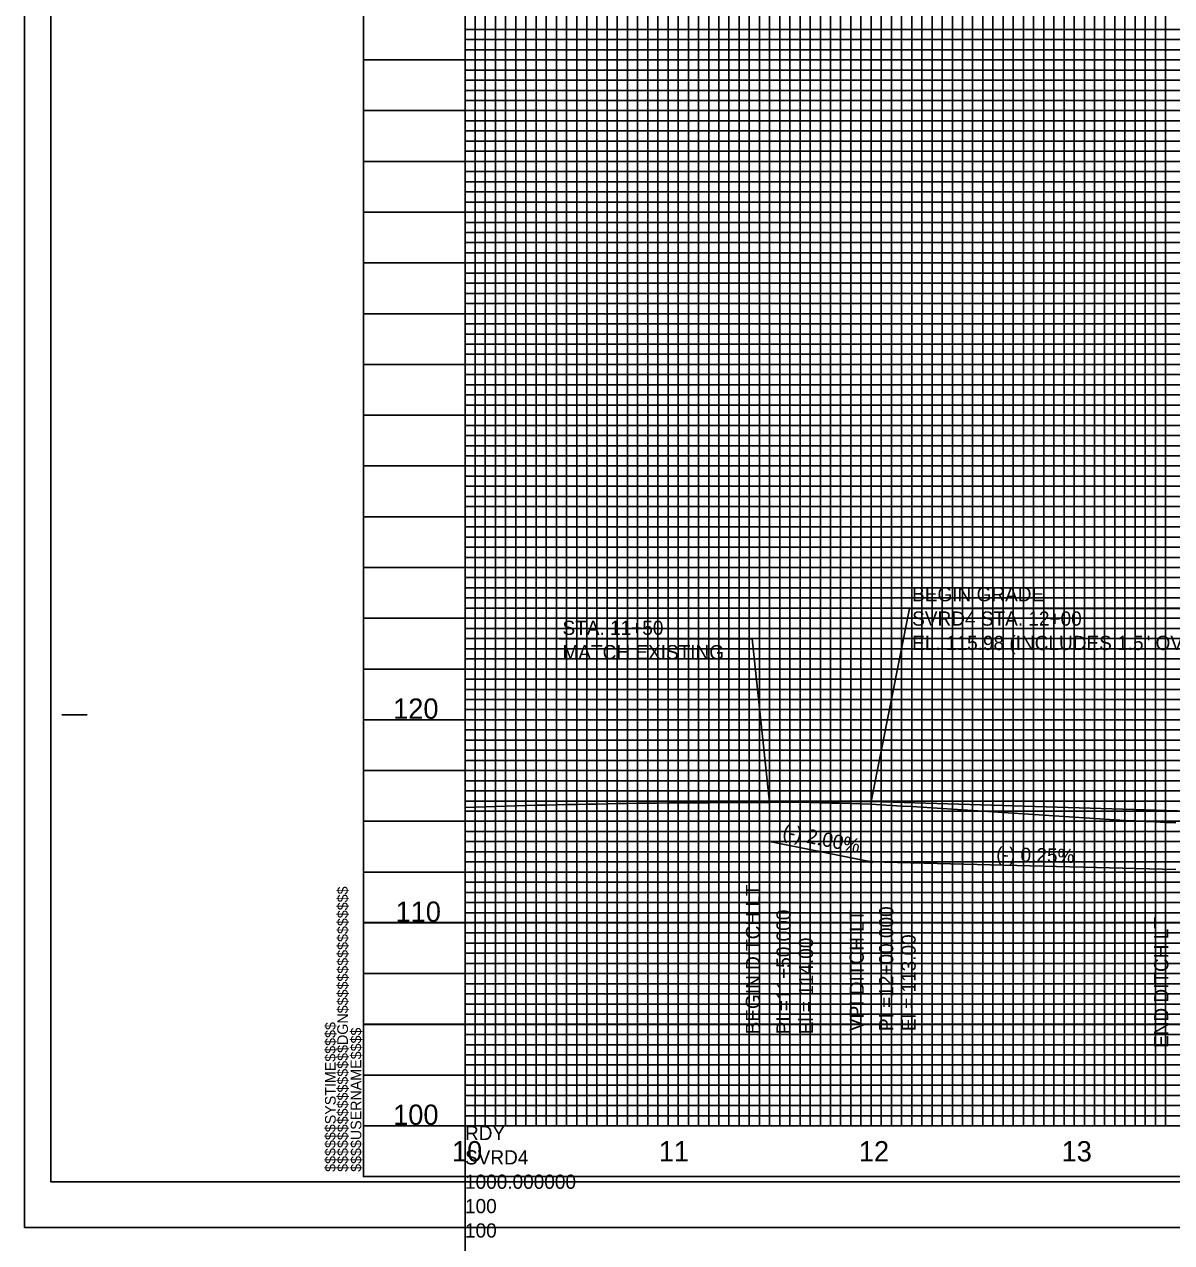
# Model space of a CAD drawing. Extents: x 2345490 to 2436403, y 465165 to 573888.
# Drawn here: x 2381550 to 2382115, y 495035 to 495635 of the extents above; entities that cross this region are included whole.
import ezdxf

# ---------------------------------------------------------------- set-up
doc = ezdxf.new("R2010")
doc.units = 0
for name, color, linetype in [('Old_Level_1', 7, 'Continuous'), ('Old_Level_18', 7, 'Continuous'), ('Old_Level_2', 7, 'Continuous'), ('Old_Level_3', 7, 'Continuous'), ('Old_Level_40', 7, 'Continuous'), ('Old_Level_41', 7, 'Continuous'), ('Old_Level_42', 7, 'Continuous'), ('Old_Level_43', 7, 'Continuous'), ('Old_Level_50', 7, 'Continuous'), ('Old_Level_51', 7, 'Continuous'), ('Old_Level_52', 7, 'Continuous'), ('Old_Level_57', 7, 'Continuous'), ('Old_Level_62', 7, 'Continuous'), ('Old_Level_63', 7, 'Continuous')]:
    doc.layers.add(name, color=color, linetype=linetype)

msp = doc.modelspace()

# ---------------------------------------------------------------- linework, layer by layer
at = {"layer": 'Old_Level_1'}
msp.add_lwpolyline([(2381766.799, 495249.40325), (2381771.799, 495249.5755), (2381776.799, 495249.74775), (2381781.799, 495249.92), (2381786.799, 495250.09225), (2381791.799, 495250.26425), (2381796.799, 495250.4135), (2381801.799, 495250.52025), (2381806.799, 495250.627), (2381811.799, 495250.7335), (2381816.799, 495250.84025), (2381821.799, 495250.947), (2381826.799, 495251.0435), (2381831.799, 495251.15), (2381836.799, 495251.25675), (2381841.799, 495251.3635), (2381846.799, 495251.47025), (2381851.799, 495251.57575), (2381856.799, 495251.61225), (2381861.799, 495251.644), (2381866.799, 495251.67575), (2381871.799, 495251.70725), (2381876.799, 495251.739), (2381881.799, 495251.77025), (2381886.799, 495251.78975), (2381891.799, 495251.8215), (2381896.799, 495251.853), (2381901.799, 495251.8845), (2381906.799, 495251.916), (2381911.799, 495251.9475), (2381916.799, 495251.979), (2381921.799, 495252.0105), (2381926.799, 495252.042), (2381931.799, 495252.0035), (2381936.799, 495251.8815), (2381941.799, 495251.75925), (2381946.799, 495251.63725), (2381951.799, 495251.51525), (2381956.799, 495251.39325), (2381961.799, 495251.27375), (2381966.799, 495251.117), (2381971.799, 495250.8055), (2381976.799, 495250.4905), (2381981.799, 495250.17525), (2381986.799, 495249.86025), (2381991.799, 495249.545), (2381996.799, 495249.23), (2382001.799, 495248.91675), (2382006.799, 495248.6015), (2382011.799, 495248.28625), (2382016.799, 495247.97075), (2382021.799, 495247.6555), (2382026.799, 495247.34025), (2382031.799, 495247.0215), (2382036.799, 495246.697), (2382041.799, 495246.37225), (2382046.799, 495246.04775), (2382051.799, 495245.723), (2382056.799, 495245.3975), (2382061.799, 495245.0645), (2382066.799, 495244.7315), (2382071.799, 495244.39825), (2382076.799, 495244.06525), (2382081.799, 495243.73225), (2382086.799, 495243.399), (2382091.799, 495243.09625), (2382096.799, 495242.8485), (2382101.799, 495242.601), (2382106.799, 495242.35325), (2382111.799, 495242.10525), (2382116.799, 495241.85425)], dxfattribs=at)
at = {"layer": 'Old_Level_18'}
msp.add_line((2381716.79875, 495067.6345), (2381716.79875, 495067.6345), dxfattribs=at)
msp.add_line((2381716.79875, 495067.6345), (2381716.79875, 495067.6345), dxfattribs=at)
msp.add_lwpolyline([(2383216.79875, 496117.6345), (2381716.79875, 496117.6345), (2381716.79875, 495067.6345), (2383216.79875, 495067.6345)], close=True, dxfattribs=at)
at = {"layer": 'Old_Level_2'}
for p, q in [((2381966.799, 495252.4345), (2381985.7585, 495347.449)), ((2381985.7585, 495347.449), (2382194.836, 495347.449)), ((2381813.15575, 495332.47475), (2381908.162, 495332.47475)), ((2381916.79875, 495251.979), (2381908.162, 495332.47475)), ((2381966.799, 495252.4345), (2381916.79875, 495251.979)), ((2381966.799, 495252.4345), (2382191.799, 495245.4595))]:
    msp.add_line(p, q, dxfattribs=at)
at = {"layer": 'Old_Level_3'}
for p, q in [((2381916.799, 495232.6345), (2381966.799, 495222.6345)), ((2381916.799, 495232.6345), (2381916.799, 495136.33353)), ((2381966.799, 495222.6345), (2382116.799, 495218.9345)), ((2381966.799, 495222.6345), (2381966.799, 495136.87267))]:
    msp.add_line(p, q, dxfattribs=at)
msp.add_circle((2381966.799, 495222.6345), 0.5, dxfattribs=at)
at = {"layer": 'Old_Level_40'}
msp.add_line((2381716.79875, 495067.6345), (2381716.79875, 495067.6345), dxfattribs=at)
msp.add_line((2381716.79875, 495067.6345), (2381716.79875, 495067.6345), dxfattribs=at)
msp.add_line((2381716.79875, 495067.6345), (2381716.79875, 495067.6345), dxfattribs=at)
msp.add_line((2381716.79875, 495067.6345), (2381716.79875, 495067.6345), dxfattribs=at)
at = {"layer": 'Old_Level_41'}
for p, q in [((2381568.29875, 495295.1345), (2381580.79875, 495295.1345)), ((2383216.79875, 495092.6345), (2381716.79875, 495092.6345))]:
    msp.add_line(p, q, dxfattribs=at)
for points in [[(2381716.79875, 496117.6345), (2381766.79875, 496117.6345), (2381766.79875, 495092.6345), (2381816.79875, 495092.6345), (2381816.79875, 496117.6345), (2381866.79875, 496117.6345), (2381866.79875, 495092.6345), (2381916.79875, 495092.6345), (2381916.79875, 496117.6345), (2381966.79875, 496117.6345), (2381966.79875, 495092.6345), (2382016.79875, 495092.6345), (2382016.79875, 496117.6345), (2382066.79875, 496117.6345), (2382066.79875, 495092.6345), (2382116.79875, 495092.6345)], [(2381791.79875, 495092.6345), (2381791.79875, 496117.6345), (2381841.79875, 496117.6345), (2381841.79875, 495092.6345), (2381891.79875, 495092.6345), (2381891.79875, 496117.6345), (2381941.79875, 496117.6345), (2381941.79875, 495092.6345), (2381991.79875, 495092.6345), (2381991.79875, 496117.6345), (2382041.79875, 496117.6345), (2382041.79875, 495092.6345), (2382091.79875, 495092.6345), (2382091.79875, 496117.6345), (2382141.79875, 496117.6345)], [(2383216.79875, 495617.6345), (2381716.79875, 495617.6345), (2381716.79875, 495567.6345), (2383216.79875, 495567.6345)], [(2383216.79875, 495517.6345), (2381716.79875, 495517.6345), (2381716.79875, 495467.6345), (2383216.79875, 495467.6345)], [(2383216.79875, 495442.6345), (2381716.79875, 495442.6345), (2381716.79875, 495492.6345), (2383216.79875, 495492.6345)], [(2383216.79875, 495417.6345), (2381716.79875, 495417.6345), (2381716.79875, 495367.6345), (2383216.79875, 495367.6345)], [(2383216.79875, 495342.6345), (2381716.79875, 495342.6345), (2381716.79875, 495392.6345), (2383216.79875, 495392.6345)], [(2383216.79875, 495317.6345), (2381716.79875, 495317.6345), (2381716.79875, 495267.6345), (2383216.79875, 495267.6345)], [(2383216.79875, 495217.6345), (2381716.79875, 495217.6345), (2381716.79875, 495167.6345), (2383216.79875, 495167.6345)], [(2383216.79875, 495142.6345), (2381716.79875, 495142.6345), (2381716.79875, 495192.6345), (2383216.79875, 495192.6345)], [(2383216.79875, 495117.6345), (2381716.79875, 495117.6345)], [(2381754.29875, 495067.6345), (2381754.29875, 495067.6345)]]:
    msp.add_lwpolyline(points, dxfattribs=at)
at = {"layer": 'Old_Level_42'}
for points in [[(2383216.79875, 495542.6345), (2381716.79875, 495542.6345), (2381716.79875, 495592.6345), (2383216.79875, 495592.6345)], [(2383216.79875, 495242.6345), (2381716.79875, 495242.6345), (2381716.79875, 495292.6345), (2383216.79875, 495292.6345)]]:
    msp.add_lwpolyline(points, dxfattribs=at)
at = {"layer": 'Old_Level_43'}
for points in [[(2381771.79875, 496117.6345), (2381771.79875, 495092.6345), (2381776.79875, 495092.6345), (2381776.79875, 496117.6345)], [(2381781.79875, 496117.6345), (2381781.79875, 495092.6345), (2381786.79875, 495092.6345), (2381786.79875, 496117.6345)], [(2381796.79875, 496117.6345), (2381796.79875, 495092.6345), (2381801.79875, 495092.6345), (2381801.79875, 496117.6345)], [(2381806.79875, 496117.6345), (2381806.79875, 495092.6345), (2381811.79875, 495092.6345), (2381811.79875, 496117.6345)], [(2381821.79875, 496117.6345), (2381821.79875, 495092.6345), (2381826.79875, 495092.6345), (2381826.79875, 496117.6345)], [(2381831.79875, 496117.6345), (2381831.79875, 495092.6345), (2381836.79875, 495092.6345), (2381836.79875, 496117.6345)], [(2381846.79875, 496117.6345), (2381846.79875, 495092.6345), (2381851.79875, 495092.6345), (2381851.79875, 496117.6345)], [(2381856.79875, 496117.6345), (2381856.79875, 495092.6345), (2381861.79875, 495092.6345), (2381861.79875, 496117.6345)], [(2381871.79875, 496117.6345), (2381871.79875, 495092.6345), (2381876.79875, 495092.6345), (2381876.79875, 496117.6345)], [(2381881.79875, 496117.6345), (2381881.79875, 495092.6345), (2381886.79875, 495092.6345), (2381886.79875, 496117.6345)], [(2381896.79875, 496117.6345), (2381896.79875, 495092.6345), (2381901.79875, 495092.6345), (2381901.79875, 496117.6345)], [(2381906.79875, 496117.6345), (2381906.79875, 495092.6345), (2381911.79875, 495092.6345), (2381911.79875, 496117.6345)], [(2381921.79875, 496117.6345), (2381921.79875, 495092.6345), (2381926.79875, 495092.6345), (2381926.79875, 496117.6345)], [(2381931.79875, 495092.6345), (2381936.79875, 495092.6345), (2381936.79875, 496117.6345)], [(2381931.79875, 496117.6345), (2381931.79875, 495092.6345)], [(2381946.79875, 496117.6345), (2381946.79875, 495092.6345), (2381951.79875, 495092.6345), (2381951.79875, 496117.6345)], [(2381956.79875, 496117.6345), (2381956.79875, 495092.6345), (2381961.79875, 495092.6345), (2381961.79875, 496117.6345)], [(2381971.79875, 496117.6345), (2381971.79875, 495092.6345), (2381976.79875, 495092.6345), (2381976.79875, 496117.6345)], [(2381981.79875, 496117.6345), (2381981.79875, 495092.6345), (2381986.79875, 495092.6345), (2381986.79875, 496117.6345)], [(2381996.79875, 496117.6345), (2381996.79875, 495092.6345), (2382001.79875, 495092.6345), (2382001.79875, 496117.6345)], [(2382006.79875, 496117.6345), (2382006.79875, 495092.6345), (2382011.79875, 495092.6345), (2382011.79875, 496117.6345)], [(2382021.79875, 496117.6345), (2382021.79875, 495092.6345), (2382026.79875, 495092.6345), (2382026.79875, 496117.6345)], [(2382031.79875, 496117.6345), (2382031.79875, 495092.6345), (2382036.79875, 495092.6345), (2382036.79875, 496117.6345)], [(2382046.79875, 496117.6345), (2382046.79875, 495092.6345), (2382051.79875, 495092.6345), (2382051.79875, 496117.6345)], [(2382056.79875, 496117.6345), (2382056.79875, 495092.6345), (2382061.79875, 495092.6345), (2382061.79875, 496117.6345)], [(2382071.79875, 496117.6345), (2382071.79875, 495092.6345), (2382076.79875, 495092.6345), (2382076.79875, 496117.6345)], [(2382081.79875, 496117.6345), (2382081.79875, 495092.6345), (2382086.79875, 495092.6345), (2382086.79875, 496117.6345)], [(2382096.79875, 496117.6345), (2382096.79875, 495092.6345), (2382111.79875, 495092.6345), (2382111.79875, 496117.6345)], [(2382101.79875, 496117.6345), (2382101.79875, 495092.6345), (2382106.79875, 495092.6345), (2382106.79875, 496117.6345)], [(2382101.79875, 496117.0345), (2382101.79875, 495092.6345), (2382106.79875, 495092.6345), (2382106.79875, 496117.0345)], [(2383166.79875, 495632.6345), (2381766.79875, 495632.6345), (2381766.79875, 495627.6345), (2383166.79875, 495627.6345)], [(2383166.79875, 495622.6345), (2381766.79875, 495622.6345), (2381766.79875, 495612.6345), (2383166.79875, 495612.6345)], [(2383166.79875, 495607.6345), (2381766.79875, 495607.6345), (2381766.79875, 495602.6345), (2383166.79875, 495602.6345)], [(2383166.79875, 495597.6345), (2381766.79875, 495597.6345)], [(2381766.79875, 495587.6345), (2383166.79875, 495587.6345)], [(2383166.79875, 495582.6345), (2381766.79875, 495582.6345), (2381766.79875, 495577.6345), (2383166.79875, 495577.6345)], [(2383166.79875, 495572.6345), (2381766.79875, 495572.6345), (2381766.79875, 495562.6345), (2383166.79875, 495562.6345)], [(2383166.79875, 495557.6345), (2381766.79875, 495557.6345), (2381766.79875, 495552.6345), (2383166.79875, 495552.6345)], [(2383166.79875, 495547.6345), (2381766.79875, 495547.6345), (2381766.79875, 495537.6345), (2383166.79875, 495537.6345)], [(2383166.79875, 495532.6345), (2381766.79875, 495532.6345), (2381766.79875, 495527.6345), (2383166.79875, 495527.6345)], [(2383166.79875, 495522.6345), (2381766.79875, 495522.6345), (2381766.79875, 495512.6345), (2383166.79875, 495512.6345)], [(2383166.79875, 495507.6345), (2381766.79875, 495507.6345), (2381766.79875, 495502.6345), (2383166.79875, 495502.6345)], [(2383166.79875, 495497.6345), (2381766.79875, 495497.6345), (2381766.79875, 495487.6345), (2383166.79875, 495487.6345)], [(2383166.79875, 495482.6345), (2381766.79875, 495482.6345), (2381766.79875, 495477.6345), (2383166.79875, 495477.6345)], [(2383166.79875, 495472.6345), (2381766.79875, 495472.6345), (2381766.79875, 495462.6345), (2383166.79875, 495462.6345)], [(2383166.79875, 495457.6345), (2381766.79875, 495457.6345), (2381766.79875, 495452.6345), (2383166.79875, 495452.6345)], [(2383166.79875, 495447.6345), (2381766.79875, 495447.6345), (2381766.79875, 495437.6345), (2383166.79875, 495437.6345)], [(2383166.79875, 495432.6345), (2381766.79875, 495432.6345), (2381766.79875, 495427.6345), (2383166.79875, 495427.6345)], [(2383166.79875, 495422.6345), (2381766.79875, 495422.6345), (2381766.79875, 495412.6345), (2383166.79875, 495412.6345)], [(2383166.79875, 495407.6345), (2381766.79875, 495407.6345), (2381766.79875, 495402.6345), (2383166.79875, 495402.6345)], [(2383166.79875, 495397.6345), (2381766.79875, 495397.6345), (2381766.79875, 495387.6345), (2383166.79875, 495387.6345)], [(2383166.79875, 495382.6345), (2381766.79875, 495382.6345), (2381766.79875, 495377.6345), (2383166.79875, 495377.6345)], [(2383166.79875, 495372.6345), (2381766.79875, 495372.6345), (2381766.79875, 495362.6345), (2383166.79875, 495362.6345)], [(2383166.79875, 495357.6345), (2381766.79875, 495357.6345), (2381766.79875, 495352.6345), (2383166.79875, 495352.6345)], [(2383166.79875, 495347.6345), (2381766.79875, 495347.6345), (2381766.79875, 495337.6345), (2383166.79875, 495337.6345)], [(2383166.79875, 495332.6345), (2381766.79875, 495332.6345), (2381766.79875, 495327.6345), (2383166.79875, 495327.6345)], [(2383166.79875, 495322.6345), (2381766.79875, 495322.6345), (2381766.79875, 495312.6345), (2383166.79875, 495312.6345)], [(2383166.79875, 495307.6345), (2381766.79875, 495307.6345), (2381766.79875, 495302.6345), (2383166.79875, 495302.6345)], [(2383166.79875, 495297.6345), (2381766.79875, 495297.6345)], [(2381766.79875, 495287.6345), (2383166.79875, 495287.6345)], [(2383166.79875, 495282.6345), (2381766.79875, 495282.6345), (2381766.79875, 495277.6345), (2383166.79875, 495277.6345)], [(2383166.79875, 495272.6345), (2381766.79875, 495272.6345)], [(2381766.79875, 495262.6345), (2383166.79875, 495262.6345)], [(2383166.79875, 495257.6345), (2381766.79875, 495257.6345), (2381766.79875, 495252.6345), (2383166.79875, 495252.6345)], [(2383166.79875, 495247.6345), (2381766.79875, 495247.6345), (2381766.79875, 495237.6345), (2383166.79875, 495237.6345)], [(2383166.79875, 495232.6345), (2381766.79875, 495232.6345), (2381766.79875, 495227.6345), (2383166.79875, 495227.6345)], [(2383166.79875, 495222.6345), (2381766.79875, 495222.6345), (2381766.79875, 495212.6345), (2383166.79875, 495212.6345)], [(2383166.79875, 495207.6345), (2381766.79875, 495207.6345), (2381766.79875, 495202.6345), (2383166.79875, 495202.6345)], [(2383166.79875, 495197.6345), (2381766.79875, 495197.6345), (2381766.79875, 495187.6345), (2383166.79875, 495187.6345)], [(2383166.79875, 495182.6345), (2381766.79875, 495182.6345), (2381766.79875, 495177.6345), (2383166.79875, 495177.6345)], [(2383166.79875, 495172.6345), (2381766.79875, 495172.6345), (2381766.79875, 495162.6345), (2383166.79875, 495162.6345)], [(2383166.79875, 495157.6345), (2381766.79875, 495157.6345), (2381766.79875, 495152.6345), (2383166.79875, 495152.6345)], [(2383166.79875, 495147.6345), (2381766.79875, 495147.6345), (2381766.79875, 495137.6345), (2383166.79875, 495137.6345)], [(2383166.79875, 495132.6345), (2381766.79875, 495132.6345), (2381766.79875, 495127.6345), (2383166.79875, 495127.6345)], [(2383166.79875, 495122.6345), (2381766.79875, 495122.6345), (2381766.79875, 495112.6345), (2383166.79875, 495112.6345)], [(2383166.79875, 495107.6345), (2381766.79875, 495107.6345), (2381766.79875, 495102.6345), (2383166.79875, 495102.6345)], [(2383166.79875, 495097.6345), (2381766.79875, 495097.6345)]]:
    msp.add_lwpolyline(points, dxfattribs=at)
at = {"layer": 'Old_Level_50'}
msp.add_line((2381549.79875, 495042.6345), (2381549.79875, 495042.6345), dxfattribs=at)
msp.add_lwpolyline([(2383229.29875, 496120.1845), (2381562.79875, 496120.1845), (2381562.79875, 495065.0845), (2383229.29875, 495065.0845)], close=True, dxfattribs=at)
at = {"layer": 'Old_Level_51'}
msp.add_lwpolyline([(2383233.79875, 496142.6345), (2381549.79875, 496142.6345), (2381549.79875, 495042.6345), (2383233.79875, 495042.6345)], close=True, dxfattribs=at)
at = {"layer": 'Old_Level_52'}
msp.add_line((2381562.79875, 495065.0845), (2381562.79875, 495065.0845), dxfattribs=at)
at = {"layer": 'Old_Level_57'}
for p, q in [((2381716.79925, 495392.63475), (2382966.79875, 495392.63475)), ((2381766.79875, 495092.63475), (2381766.79875, 495392.63475)), ((2381766.79875, 495092.73475), (2381766.79875, 495392.63475)), ((2381866.79875, 495092.63475), (2381866.79875, 495392.63475)), ((2381866.79875, 495092.63475), (2381866.79875, 495392.63475)), ((2381866.79875, 495092.73475), (2381866.79875, 495392.63475)), ((2381866.79875, 495092.73475), (2381866.79875, 495392.63475)), ((2381966.79875, 495092.63475), (2381966.79875, 495392.63475)), ((2381966.79875, 495092.63475), (2381966.79875, 495392.63475)), ((2381966.79875, 495092.63475), (2381966.79875, 495392.63475)), ((2381966.79875, 495092.73475), (2381966.79875, 495392.63475)), ((2381966.79875, 495092.73475), (2381966.79875, 495392.63475)), ((2381966.79875, 495092.73475), (2381966.79875, 495392.63475)), ((2382066.79875, 495092.63475), (2382066.79875, 495392.63475)), ((2382066.79875, 495092.63475), (2382066.79875, 495392.63475)), ((2382066.79875, 495092.63475), (2382066.79875, 495392.63475)), ((2382066.79875, 495092.63475), (2382066.79875, 495392.63475)), ((2382066.79875, 495092.73475), (2382066.79875, 495392.63475)), ((2382066.79875, 495092.73475), (2382066.79875, 495392.63475)), ((2382066.79875, 495092.73475), (2382066.79875, 495392.63475)), ((2382066.79875, 495092.73475), (2382066.79875, 495392.63475)), ((2381716.79925, 495342.63475), (2382966.79875, 495342.63475)), ((2381716.79925, 495292.63475), (2382966.79875, 495292.63475)), ((2381716.79925, 495242.63475), (2382966.79875, 495242.63475)), ((2381716.79925, 495192.73475), (2382966.79875, 495192.73475)), ((2381716.79925, 495192.63475), (2382966.79875, 495192.63475)), ((2381816.79925, 495192.73475), (2382966.79875, 495192.73475)), ((2381816.79925, 495192.63475), (2382966.79875, 495192.63475)), ((2381916.79925, 495192.73475), (2382966.79875, 495192.73475)), ((2381916.79925, 495192.63475), (2382966.79875, 495192.63475)), ((2382016.79925, 495192.73475), (2382966.79875, 495192.73475)), ((2382016.79925, 495192.63475), (2382966.79875, 495192.63475)), ((2381716.799, 495142.73475), (2382966.79875, 495142.73475)), ((2381716.799, 495142.63475), (2382966.79875, 495142.63475)), ((2381816.799, 495142.73475), (2382966.79875, 495142.73475)), ((2381816.799, 495142.63475), (2382966.79875, 495142.63475)), ((2381916.799, 495142.73475), (2382966.79875, 495142.73475)), ((2381916.799, 495142.63475), (2382966.79875, 495142.63475)), ((2382016.799, 495142.73475), (2382966.79875, 495142.73475)), ((2382016.799, 495142.63475), (2382966.79875, 495142.63475)), ((2381716.79925, 495092.73475), (2382966.79875, 495092.73475)), ((2381716.79925, 495092.63475), (2382966.79875, 495092.63475)), ((2381816.79925, 495092.73475), (2382966.79875, 495092.73475)), ((2381816.79925, 495092.63475), (2382966.79875, 495092.63475)), ((2381916.79925, 495092.73475), (2382966.79875, 495092.73475)), ((2381916.79925, 495092.63475), (2382966.79875, 495092.63475)), ((2382016.79925, 495092.73475), (2382966.79875, 495092.73475)), ((2382016.79925, 495092.63475), (2382966.79875, 495092.63475))]:
    msp.add_line(p, q, dxfattribs=at)
at = {"layer": 'Old_Level_63'}
for q in [(2381766.79875, 497592.6345), (2382911.238, 495092.6345), (2381766.79875, 492592.6345)]:
    msp.add_line((2381766.79875, 495092.6345), q, dxfattribs=at)

# ---------------------------------------------------------------- texts
at = {"layer": 'Old_Level_2'}
for s, height, p in [('BEGIN GRADE', 7.0000005, (2381987.00925, 495350.99225)), ('SVRD4 STA. 12+00', 7.0000005, (2381987.00925, 495338.99225)), ('STA. 11+50', 7.000001, (2381814.81725, 495334.44325)), ('EL. 115.98 (INCLUDES 1.5" OVERLAY)', 7.0000005, (2381987.00925, 495326.99225)), ('MATCH EXISTING', 7.0000005, (2381814.81725, 495322.44325))]:
    msp.add_text(s, height=height, dxfattribs=at).set_placement(p)
at = {"layer": 'Old_Level_3'}
for s, height, rotation, p in [('(-) 2.00%', 7, 348.69006667, (2381922.82271, 495234.50476)), ('(-) 0.25%', 7.000001, 358.58699167, (2382028.34913, 495222.98315)), ('BEGIN DITCH LT', 7.0000005, 90, (2381912.10331, 495137.7126)), ('PI =11+50.000', 7.0000005, 90, (2381927.19918, 495137.7126)), ('VPI DITCH LT', 7.0000005, 90, (2381963.18158, 495139.33235)), ('PI =12+00.000', 7.0000005, 90, (2381977.73832, 495139.33235)), ('END DITCH LT', 7.0000005, 90, (2382113.18158, 495130.99608)), ('El = 114.00', 7.0000005, 90, (2381938.19918, 495137.7126)), ('El = 113.00', 7.0000005, 90, (2381988.73832, 495139.33235))]:
    msp.add_text(s, height=height, rotation=rotation, dxfattribs=at).set_placement(p)
at = {"layer": 'Old_Level_41'}
for s, p in [('$$$$$$$$$$$$$$$$DGN$$$$$$$$$$$$$$$$', (2381709.14875, 495069.997)), ('$$$$$$SYSTIME$$$$$', (2381703.09875, 495069.997)), ('$$$$USERNAME$$$$', (2381715.72375, 495070.0095))]:
    msp.add_text(s, height=5.25, rotation=90, dxfattribs=at).set_placement(p)
at = {"layer": 'Old_Level_62'}
for s, p in [('120', (2381731.428, 495293.1345)), ('110', (2381732.62475, 495193.1345)), ('100', (2381731.428, 495093.1345)), ('10', (2381760.3825, 495075.1345)), ('11', (2381862.222, 495075.1345)), ('12', (2381960.77025, 495075.1345)), ('13', (2382060.605, 495075.1345))]:
    msp.add_text(s, height=10.000001, dxfattribs=at).set_placement(p)
at = {"layer": 'Old_Level_63'}
for s, height, p in [('RDY', 7.000001, (2381766.79875, 495085.6345)), ('SVRD4', 7.000001, (2381766.79875, 495073.6345)), ('1000.000000', 7.0000005, (2381766.79875, 495061.6345)), ('100', 7.000001, (2381766.79875, 495049.6345)), ('100', 7.000001, (2381766.79875, 495037.6345))]:
    msp.add_text(s, height=height, dxfattribs=at).set_placement(p)

doc.saveas('drawing.dxf')
